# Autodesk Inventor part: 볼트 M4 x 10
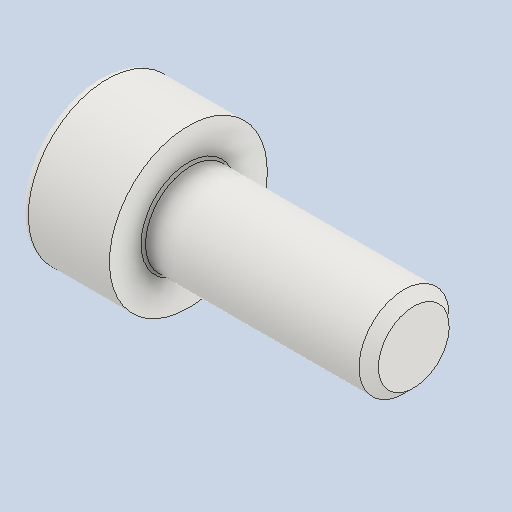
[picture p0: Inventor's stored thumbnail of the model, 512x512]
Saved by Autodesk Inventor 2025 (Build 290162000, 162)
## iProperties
Created: 2024-07
Part Number: 볼트 M4 x 10
Material: 강철, 연강
Description: 6각머리 태핑 나사
Document SubType Name: Modeling
Designer: hsj03
Density: 7.86 g/cm^3
Appearance: 기본값
Author: jhkim
Revision Number: 1
Sending System: Autodesk Inventor 2025
Preprocessor: ST-DEVELOPER v20
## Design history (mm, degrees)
feature "Solid1"
node "솔리드1"
